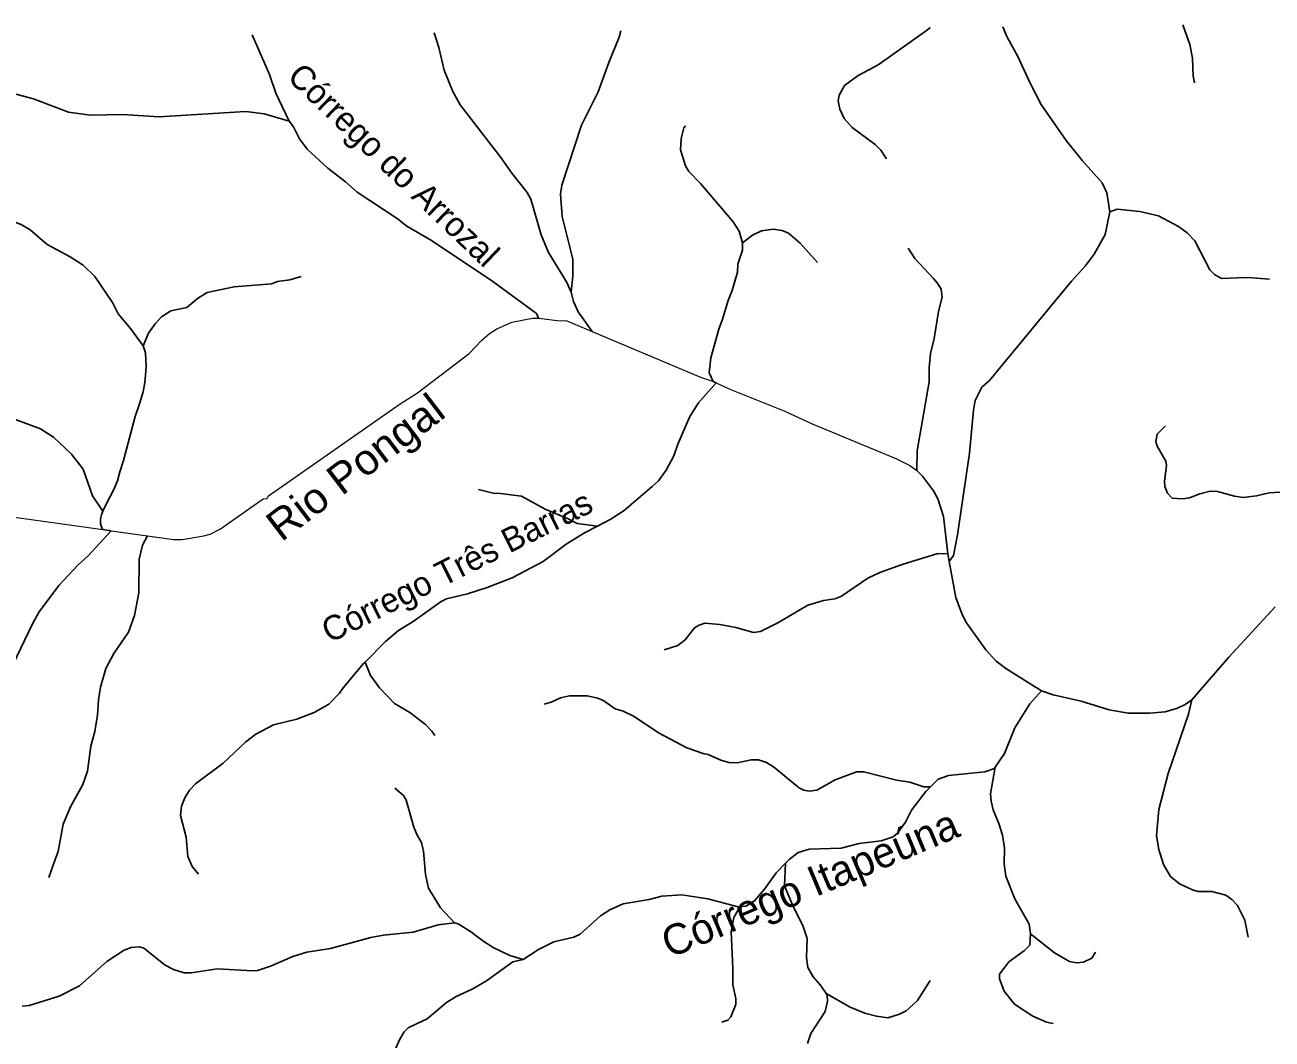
# Model space of a CAD drawing. Extents: x 317.8 to 344.1, y 7676.8 to 7704.8.
# Drawn here: x 321.463 to 325.558, y 7701.254 to 7704.584 of the extents above; entities that cross this region are included whole.
import ezdxf
from ezdxf.enums import TextEntityAlignment as Align

# ---------------------------------------------------------------- set-up
doc = ezdxf.new("R2010")
doc.units = 0
doc.header["$LTSCALE"] = 0.032
doc.layers.add('1', color=7, linetype='Continuous', lineweight=13)
doc.layers.add('7', color=7, linetype='Continuous', lineweight=25)
doc.layers.add('61', color=7, linetype='Continuous')

msp = doc.modelspace()

# ---------------------------------------------------------------- linework, layer by layer
at = {"layer": '1'}
msp.add_line((321.7458, 7702.9232), (321.8656, 7702.9065), dxfattribs=at)
for points in [[(321.8656, 7702.9065), (321.9513, 7702.8945), (321.979, 7702.8945), (322.0507, 7702.906), (322.0714, 7702.9124), (322.105, 7702.9294), (322.246, 7703.0279), (322.2584, 7703.0292), (322.2625, 7703.0384), (322.6955, 7703.3398), (322.7521, 7703.3759), (322.9223, 7703.5052), (322.9638, 7703.5492), (322.9887, 7703.5706), (323.0131, 7703.586), (323.0625, 7703.6079), (323.1303, 7703.6214), (323.1501, 7703.6209)], [(323.1501, 7703.6209), (323.1595, 7703.6207), (323.2113, 7703.6134), (323.2427, 7703.6124), (323.326, 7703.5774)], [(323.326, 7703.5774), (323.6819, 7703.428), (323.7182, 7703.4155), (323.7233, 7703.4132)], [(323.7335, 7703.4085), (323.7781, 7703.3882), (323.958, 7703.3159), (323.9603, 7703.315), (324.0486, 7703.2748), (324.3225, 7703.16), (324.3687, 7703.1376), (324.3917, 7703.1213)], [(320.9717, 7703.035), (321.3079, 7702.9842), (321.3848, 7702.9759), (321.4363, 7702.9663), (321.7192, 7702.9269)]]:
    msp.add_lwpolyline(points, dxfattribs=at)
at = {"layer": '7'}
for p, q in [((323.7233, 7703.4132), (323.7335, 7703.4085)), ((321.7192, 7702.9269), (321.7458, 7702.9232))]:
    msp.add_line(p, q, dxfattribs=at)
for points in [[(323.2574, 7703.7071), (323.2416, 7703.7409), (323.1827, 7703.8374), (323.1581, 7703.8953), (323.1241, 7704.0115), (323.1127, 7704.0343), (323.0619, 7704.0969), (323.0264, 7704.1493), (322.8923, 7704.3221), (322.8683, 7704.3652), (322.8402, 7704.4361), (322.8228, 7704.5102), (322.8071, 7704.5584)], [(323.4202, 7704.5649), (323.4145, 7704.5439), (323.3801, 7704.4604), (323.3457, 7704.364), (323.2904, 7704.2545), (323.2257, 7704.058), (323.2219, 7704.0285), (323.2268, 7703.9549), (323.2619, 7703.8155), (323.2626, 7703.7593), (323.2574, 7703.7071)], [(324.4356, 7704.5755), (324.4271, 7704.5683), (324.2687, 7704.4554), (324.2526, 7704.4468), (324.1997, 7704.4183), (324.1543, 7704.3851), (324.1369, 7704.3539), (324.1338, 7704.3348), (324.1387, 7704.3073), (324.1536, 7704.2773), (324.1793, 7704.2469), (324.2556, 7704.1917), (324.274, 7704.1726), (324.2921, 7704.1448)], [(325.0258, 7703.9704), (325.0159, 7704.0324), (325.0002, 7704.0656), (324.9361, 7704.1376), (324.8827, 7704.205), (324.8577, 7704.2409), (324.8007, 7704.3225), (324.764, 7704.393), (324.7233, 7704.481), (324.6882, 7704.5445), (324.6744, 7704.578)], [(325.2651, 7704.5841), (325.2888, 7704.5201), (325.2969, 7704.4755), (325.2994, 7704.4162), (325.3035, 7704.3942)], [(322.3312, 7704.2681), (322.2872, 7704.3605), (322.2665, 7704.4213), (322.2093, 7704.5521)], [(322.3312, 7704.2681), (322.2484, 7704.2923), (322.1969, 7704.2991), (322.1875, 7704.3003), (321.904, 7704.2824), (321.7836, 7704.2898), (321.6788, 7704.2874), (321.6061, 7704.2973), (321.4911, 7704.341), (321.4044, 7704.3647), (321.3432, 7704.3753), (321.2586, 7704.3771)], [(323.1501, 7703.6209), (323.1427, 7703.6361), (322.9996, 7703.7417), (322.7985, 7703.8763), (322.7176, 7703.9235), (322.6858, 7703.9486), (322.5537, 7704.0352), (322.5159, 7704.0691), (322.4577, 7704.1143), (322.3896, 7704.1766), (322.3652, 7704.2102), (322.3451, 7704.2494), (322.3312, 7704.2681)], [(323.6319, 7704.2532), (323.627, 7704.2462), (323.6181, 7704.2111), (323.6155, 7704.1741), (323.6326, 7704.121), (323.6433, 7704.1028), (323.6815, 7704.0632), (323.7887, 7703.9374), (323.8083, 7703.9072), (323.8199, 7703.8681)], [(321.8515, 7703.5299), (321.8095, 7703.5872), (321.7692, 7703.6355), (321.7581, 7703.6579), (321.751, 7703.6723), (321.6927, 7703.7578), (321.6541, 7703.7948), (321.612, 7703.8232), (321.5361, 7703.8629), (321.4804, 7703.9108), (321.4511, 7703.929), (321.3261, 7703.9755), (321.2015, 7703.9973)], [(324.4983, 7702.8226), (324.5128, 7702.8419), (324.5258, 7702.9093), (324.5651, 7703.178), (324.5781, 7703.3191), (324.5836, 7703.3511), (324.6053, 7703.3942), (324.6305, 7703.4163), (324.8996, 7703.7425), (324.9452, 7703.792), (324.9748, 7703.831), (325.0105, 7703.8955), (325.0258, 7703.9704)], [(325.0258, 7703.9704), (325.0497, 7703.9793), (325.1241, 7703.9718), (325.1855, 7703.9568), (325.2513, 7703.9223), (325.2795, 7703.9013), (325.3048, 7703.8752), (325.3546, 7703.7804), (325.3694, 7703.7647), (325.392, 7703.7519), (325.4443, 7703.7538), (325.4802, 7703.7551), (325.5505, 7703.7495)], [(323.8199, 7703.8681), (323.8523, 7703.8942), (323.8817, 7703.9082), (323.9205, 7703.9132), (323.9502, 7703.9092), (323.9704, 7703.9008), (324.0094, 7703.8674), (324.0655, 7703.8041)], [(323.8199, 7703.8681), (323.8192, 7703.8443), (323.8047, 7703.7983), (323.8034, 7703.7723), (323.7861, 7703.7126), (323.7722, 7703.6796), (323.7541, 7703.6177), (323.7413, 7703.5855), (323.715, 7703.4905), (323.7101, 7703.4413), (323.7233, 7703.4132)], [(324.3917, 7703.1213), (324.3926, 7703.1857), (324.4321, 7703.4121), (324.4322, 7703.4595), (324.4371, 7703.5052), (324.4492, 7703.5549), (324.4631, 7703.6431), (324.4753, 7703.6898), (324.4722, 7703.7165), (324.4589, 7703.7378), (324.4466, 7703.7511), (324.3851, 7703.8177), (324.3638, 7703.8514)], [(321.8515, 7703.5299), (321.8686, 7703.5716), (321.8907, 7703.6031), (321.9119, 7703.6259), (321.9426, 7703.6451), (321.995, 7703.6564), (322.03, 7703.6859), (322.0621, 7703.7053), (322.1507, 7703.7243), (322.2732, 7703.734), (322.2928, 7703.7412), (322.3325, 7703.7471), (322.3703, 7703.7576)], [(323.326, 7703.5774), (323.2802, 7703.6425), (323.2643, 7703.6756), (323.2574, 7703.7071)], [(321.719, 7702.9874), (321.6852, 7703.0377), (321.654, 7703.1256), (321.6163, 7703.1747), (321.5571, 7703.2308), (321.5142, 7703.2584), (321.4285, 7703.2891), (321.3727, 7703.3145), (321.3419, 7703.3436), (321.3076, 7703.3918), (321.2859, 7703.4338), (321.275, 7703.4671), (321.2202, 7703.5408), (321.1867, 7703.6077), (321.1629, 7703.6324), (321.1217, 7703.6606)], [(321.8515, 7703.5299), (321.8587, 7703.5078), (321.8603, 7703.4849), (321.8614, 7703.4625), (321.8593, 7703.4343), (321.8571, 7703.4098), (321.8513, 7703.3789), (321.8385, 7703.3363), (321.8252, 7703.2985), (321.806, 7703.2288), (321.7863, 7703.1542), (321.7746, 7703.1164), (321.7666, 7703.0872), (321.7549, 7703.0589), (321.7421, 7703.0334), (321.732, 7703.0148), (321.719, 7702.9874)], [(323.7335, 7703.4085), (323.6754, 7703.3429), (323.6468, 7703.2983), (323.6073, 7703.2078), (323.5935, 7703.1691), (323.569, 7703.1226), (323.544, 7703.0871), (323.5229, 7703.0689), (323.4307, 7702.9894), (323.3852, 7702.9606), (323.3433, 7702.9386)], [(325.2081, 7703.2678), (325.1813, 7703.2406), (325.1773, 7703.2159), (325.1809, 7703.2008), (325.2099, 7703.1519), (325.2114, 7703.1377), (325.2049, 7703.0855), (325.2064, 7703.0684), (325.2155, 7703.0464), (325.2308, 7703.0307), (325.264, 7703.0281), (325.2869, 7703.0308), (325.3211, 7703.0446), (325.355, 7703.0533), (325.3791, 7703.0524), (325.4349, 7703.0364), (325.4637, 7703.0322), (325.5076, 7703.0376), (325.5489, 7703.0475), (325.5838, 7703.0501)], [(324.3917, 7703.1213), (324.4107, 7703.1024), (324.4468, 7703.0546), (324.4606, 7703.0276), (324.4795, 7702.9699), (324.4943, 7702.847)], [(323.3433, 7702.9386), (323.2766, 7702.9468), (323.2445, 7702.9638), (323.1718, 7702.994), (323.0941, 7703.0372), (323.0165, 7703.0468), (323.0054, 7703.0455), (322.9522, 7703.0592)], [(321.719, 7702.9874), (321.7144, 7702.9754), (321.7113, 7702.9626), (321.7113, 7702.9466), (321.715, 7702.9354), (321.7192, 7702.9269)], [(321.0817, 7702.0465), (321.0906, 7702.0598), (321.0955, 7702.0672), (321.1321, 7702.1088), (321.1954, 7702.1664), (321.2247, 7702.2052), (321.2317, 7702.2196), (321.3119, 7702.3172), (321.3783, 7702.406), (321.4103, 7702.4555), (321.4891, 7702.6198), (321.5102, 7702.657), (321.5748, 7702.7437), (321.6382, 7702.8112), (321.6696, 7702.8393), (321.7458, 7702.9232)], [(323.3433, 7702.9386), (323.301, 7702.9164), (323.2408, 7702.8795), (323.1653, 7702.8226), (323.0635, 7702.7688), (322.9812, 7702.7367), (322.9163, 7702.7161), (322.8477, 7702.7001), (322.8301, 7702.6908), (322.7381, 7702.6257), (322.6899, 7702.5955), (322.6471, 7702.5592), (322.5808, 7702.4922)], [(321.5413, 7701.7851), (321.5628, 7701.844), (321.5721, 7701.8697), (321.589, 7701.9602), (321.6129, 7702.0164), (321.6528, 7702.0897), (321.6683, 7702.1337), (321.6792, 7702.2162), (321.6923, 7702.2635), (321.7018, 7702.3182), (321.7047, 7702.3684), (321.7109, 7702.4099), (321.7287, 7702.4712), (321.755, 7702.5207), (321.8028, 7702.5905), (321.8235, 7702.6449), (321.8371, 7702.7196), (321.838, 7702.8304), (321.8494, 7702.8757), (321.8656, 7702.9065)], [(324.4943, 7702.847), (324.4608, 7702.8488), (324.3434, 7702.8129), (324.271, 7702.7856), (324.2312, 7702.767), (324.1442, 7702.7085), (324.1226, 7702.6998), (324.0855, 7702.6938), (324.0339, 7702.6793), (323.9353, 7702.6211), (323.8785, 7702.5925), (323.8557, 7702.5889), (323.7979, 7702.6058), (323.7456, 7702.6157), (323.6956, 7702.6197), (323.6773, 7702.6135), (323.6618, 7702.6041), (323.631, 7702.5651), (323.6074, 7702.5467), (323.5618, 7702.5327)], [(324.4943, 7702.847), (324.4949, 7702.8416), (324.4983, 7702.8226)], [(324.4983, 7702.8226), (324.5196, 7702.7038), (324.5405, 7702.6479), (324.5546, 7702.6211), (324.6183, 7702.5321), (324.6528, 7702.4953), (324.6843, 7702.4706), (324.8017, 7702.3981)], [(325.2948, 7702.3678), (325.4161, 7702.5084), (325.5684, 7702.6735)], [(322.5808, 7702.4922), (322.5754, 7702.4868), (322.5078, 7702.4072), (322.4963, 7702.3897), (322.4612, 7702.3539), (322.4128, 7702.3261), (322.3558, 7702.3047), (322.2794, 7702.2863), (322.2218, 7702.2558), (322.1886, 7702.2306), (322.114, 7702.1606), (322.0236, 7702.0922), (322.0031, 7702.0711), (321.988, 7702.046), (321.9774, 7702.0186), (321.974, 7701.9883), (321.9925, 7701.9168), (321.9985, 7701.854), (322.0124, 7701.8205), (322.0329, 7701.7959)], [(322.5808, 7702.4922), (322.5975, 7702.4484), (322.6272, 7702.4069), (322.677, 7702.3565), (322.7269, 7702.326), (322.7785, 7702.2871), (322.7997, 7702.2652), (322.8087, 7702.2507)], [(324.8017, 7702.3981), (324.7626, 7702.3551), (324.7141, 7702.2757), (324.6795, 7702.1918), (324.6493, 7702.1471)], [(324.8017, 7702.3981), (324.8394, 7702.3849), (324.9321, 7702.3634), (325.0234, 7702.3357), (325.0856, 7702.3244), (325.1564, 7702.324), (325.2076, 7702.3289), (325.2477, 7702.3408), (325.2728, 7702.3528), (325.2948, 7702.3678)], [(323.1686, 7702.3537), (323.1915, 7702.3606), (323.2216, 7702.3747), (323.2518, 7702.3817), (323.3096, 7702.3809), (323.3442, 7702.3736), (323.3642, 7702.3643), (323.4014, 7702.3382), (323.4279, 7702.331), (323.4643, 7702.313), (323.5433, 7702.2602), (323.6369, 7702.2101), (323.6935, 7702.1903), (323.707, 7702.1883), (323.7483, 7702.1694), (323.7745, 7702.1626), (323.8025, 7702.161), (323.8479, 7702.1707), (323.8715, 7702.1708), (323.8983, 7702.1625), (323.9209, 7702.148), (323.9998, 7702.0838), (324.0039, 7702.0804), (324.0205, 7702.0718), (324.0385, 7702.0681), (324.0633, 7702.0714), (324.1233, 7702.1055), (324.1936, 7702.1316), (324.2184, 7702.1314), (324.3257, 7702.1041), (324.3691, 7702.0973), (324.4148, 7702.0827), (324.4372, 7702.0827)], [(325.48, 7701.5885), (325.4691, 7701.644), (325.4451, 7701.6932), (325.426, 7701.7129), (325.4067, 7701.7262), (325.3605, 7701.7387), (325.3146, 7701.7391), (325.2967, 7701.7438), (325.2543, 7701.7637), (325.2249, 7701.788), (325.2016, 7701.8278), (325.1864, 7701.8763), (325.1788, 7701.9218), (325.1868, 7702.0082), (325.2168, 7702.1266), (325.2845, 7702.3212), (325.2948, 7702.3678)], [(324.6493, 7702.1471), (324.6465, 7702.143), (324.6152, 7702.1315), (324.4963, 7702.1201), (324.4617, 7702.1071), (324.4372, 7702.0827)], [(324.7653, 7701.6002), (324.761, 7701.6311), (324.7138, 7701.7141), (324.684, 7701.7888), (324.6792, 7701.8298), (324.6799, 7701.8805), (324.6735, 7701.9235), (324.6614, 7701.9622), (324.6428, 7702.0064), (324.6358, 7702.0358), (324.6343, 7702.059), (324.6493, 7702.1471)], [(322.6781, 7702.0775), (322.7059, 7702.0541), (322.7156, 7702.039), (322.7407, 7701.9503), (322.7509, 7701.9239), (322.7653, 7701.8994), (322.7719, 7701.8708), (322.7783, 7701.7946), (322.7888, 7701.7501), (322.8274, 7701.6851), (322.8742, 7701.6357)], [(324.4372, 7702.0827), (324.4219, 7702.0675), (324.3745, 7702.0056), (324.3551, 7701.966), (324.3284, 7701.9303), (324.3145, 7701.9187), (324.2744, 7701.9045), (324.2029, 7701.8967), (324.1437, 7701.8809), (324.0385, 7701.8773), (324.0026, 7701.8666), (323.9729, 7701.8442), (323.9605, 7701.8316)], [(323.9605, 7701.8316), (323.9298, 7701.8004), (323.892, 7701.7464), (323.8594, 7701.708), (323.841, 7701.6967), (323.83, 7701.69), (323.8069, 7701.6878), (323.8055, 7701.6882)], [(324.0942, 7701.4033), (324.0796, 7701.4249), (324.075, 7701.4318), (324.0512, 7701.4585), (324.0339, 7701.4895), (324.0305, 7701.5147), (324.0295, 7701.5223), (324.0318, 7701.5838), (324.0173, 7701.6271), (323.9855, 7701.689), (323.9572, 7701.7572), (323.9605, 7701.8316)], [(323.8055, 7701.6882), (323.7053, 7701.7145), (323.6203, 7701.7281), (323.5541, 7701.7232), (323.5129, 7701.7125), (323.4281, 7701.698), (323.3839, 7701.6788), (323.3527, 7701.6586), (323.2865, 7701.5983), (323.2656, 7701.5887), (323.2004, 7701.5732), (323.1492, 7701.5484), (323.099, 7701.5157)], [(323.7512, 7701.3094), (323.7714, 7701.3163), (323.7814, 7701.3267), (323.798, 7701.3679), (323.7973, 7701.3869), (323.7876, 7701.4321), (323.7883, 7701.4857), (323.7826, 7701.6074), (323.7908, 7701.6534), (323.8052, 7701.6789), (323.8055, 7701.6882)], [(322.8742, 7701.6357), (322.8206, 7701.6295), (322.7385, 7701.6053), (322.6401, 7701.5953), (322.5994, 7701.5877), (322.4669, 7701.5516), (322.3886, 7701.5398), (322.3426, 7701.5252), (322.2695, 7701.4931), (322.2273, 7701.4796), (322.2116, 7701.478), (322.0942, 7701.4845), (322.0094, 7701.4716), (321.9861, 7701.4718), (321.9515, 7701.4826), (321.9237, 7701.497), (321.8532, 7701.5526), (321.839, 7701.5569), (321.8119, 7701.5544), (321.7891, 7701.5456), (321.7354, 7701.5107), (321.7317, 7701.5083), (321.6423, 7701.4288), (321.5755, 7701.3949), (321.4771, 7701.3646), (321.4536, 7701.3622)], [(323.099, 7701.5157), (323.0555, 7701.5284), (323.0008, 7701.555), (322.9663, 7701.5763), (322.9444, 7701.5935), (322.9292, 7701.6055), (322.8857, 7701.6325), (322.8742, 7701.6357)], [(324.8397, 7701.3056), (324.8176, 7701.3099), (324.7733, 7701.3297), (324.7128, 7701.3692), (324.6793, 7701.4116), (324.6635, 7701.4517), (324.6631, 7701.4676), (324.6804, 7701.4899), (324.6943, 7701.5078), (324.7454, 7701.5444), (324.7629, 7701.5622), (324.7653, 7701.6002)], [(324.9785, 7701.5392), (324.9661, 7701.5197), (324.9397, 7701.5061), (324.9168, 7701.5049), (324.893, 7701.5093), (324.8438, 7701.5375), (324.7653, 7701.6002)], [(323.099, 7701.5157), (323.0656, 7701.5073), (322.979, 7701.4453), (322.9314, 7701.4175), (322.8796, 7701.394), (322.8477, 7701.3741), (322.7837, 7701.3208), (322.7513, 7701.3054), (322.7218, 7701.2914), (322.7088, 7701.2777), (322.6943, 7701.254), (322.6716, 7701.2027)], [(324.4353, 7701.4459), (324.3944, 7701.3808), (324.3792, 7701.367), (324.3574, 7701.3472), (324.3346, 7701.3358), (324.2968, 7701.324), (324.259, 7701.3288), (324.221, 7701.3396), (324.1734, 7701.3591), (324.0942, 7701.4033)], [(324.0329, 7701.2392), (324.0436, 7701.2721), (324.0906, 7701.3444), (324.0987, 7701.3787), (324.0972, 7701.3988), (324.0942, 7701.4033)]]:
    msp.add_lwpolyline(points, dxfattribs=at)

# ---------------------------------------------------------------- texts
at = {"layer": '61'}
for s, height, rotation, p in [('Córrego do Arrozal', 0.08, 316.225, (322.6467, 7704.0961)), ('Córrego Três Barras', 0.08, 26.565, (322.8994, 7702.771)), ('Córrego Itapeúna', 0.1, 22.807, (324.0603, 7701.7202))]:
    msp.add_text(s, height=height, rotation=rotation, dxfattribs=at).set_placement(p, align=Align.CENTER)
at = {"layer": '61', "width": 1.05}
msp.add_text('Rio Pongal', height=0.1, rotation=37.304, dxfattribs=at).set_placement((322.5781, 7703.0927), align=Align.CENTER)

doc.saveas('drawing.dxf')
